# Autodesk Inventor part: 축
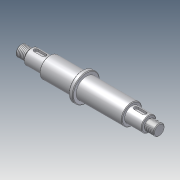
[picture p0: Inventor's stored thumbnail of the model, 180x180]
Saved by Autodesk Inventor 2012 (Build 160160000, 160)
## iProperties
Company: 한국ATC센터
Created: 2015-02
Part Number: 축
Document SubType Name: Modeling
Designer: KYOUNG IL JANG
Density: 1 g/cm^3
Material: 기본값
Author: KYOUNG IL JANG
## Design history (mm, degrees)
sketch "스케치1"
  geometry: L1 (0, 0)-(203, 0); L2 (203, 0)-(203, 8); L3 (203, 8)-(189.5, 8); L4 (189.5, 8)-(189.5, 7); L5 (189.5, 7)-(188, 7); L6 (188, 7)-(188, 11); L7 (188, 11)-(163, 11); L8 (163, 11)-(163, 15); L9 (163, 15)-(96, 15); L10 (96, 15)-(96, 20); L11 (96, 20)-(90, 20); L12 (90, 20)-(90, 15); L13 (90, 15)-(42, 15); L14 (42, 15)-(42, 11); L15 (42, 11)-(15, 11); L16 (15, 11)-(15, 7); L17 (15, 7)-(13.5, 7); L18 (0, 8)-(0, 0); L19 (0, 8)-(13.5, 8); L20 (13.5, 8)-(13.5, 7)
  constraints: 40 end point, 16 parallel, 3 perpendicular, 1 collinear, 1 horizontal
  dimensions: "d0" = 16 diameter of L3 L1; "d1" = 14 diameter of L5 L1; "d2" = 22 diameter of L7 L1; "d3" = 30 diameter of L9 L1; "d4" = 40 diameter of L11 L1; "d5" = 16 diameter of L19 L1; "d6" = 22 diameter of L15 L1; "d8" = 1.5 distance of L16.end L17.end; "d9" = 15 distance between parallel lines of L16 L18; "d10" = 27 distance between parallel lines of L14 L16; "d11" = 48 distance between parallel lines of L12 L14; "d15" = 203 distance of L1.start L1.end; "d16" = 1.5 distance of L4.end L5.end; "d17" = 14 diameter of L17 L1; "d36" = 15 distance between parallel lines of L6 L2; "d37" = 25 distance between parallel lines of L6 L8; "d38" = 6 distance between parallel lines of L10 L12
revolve "회전1" sketch "스케치1" stored, may be unused: angle "d18" = 90 deg
feature "스레드1" dims "d19" = 10, "d20" = 0
feature "스레드2" dims "d21" = 10, "d22" = 0
chamfer "모따기1" distance "d23" = 1; stored, may be unused: second distance "d24" = 2, angle "d25" = 45 deg
node "작업 평면1"
sketch "스케치2"
  geometry: L1 (-6.5, 3)-(5.5, 3); L2 (5.5, -3)-(-6.5, -3); L3 (-13.5, -10)-(-13.5, 10) reference; L4 (140.5, 3)-(152.5, 3); L5 (152.5, -3)-(140.5, -3); L6 (159.5, 10)-(159.5, -10) reference; A1 r 3 centre (5.5, 0) between (5.5, -3) and (5.5, 3); A2 r 3 centre (-6.5, 0) between (-6.5, 3) and (-6.5, -3); A3 r 3 centre (152.5, 0) between (152.5, -3) and (152.5, 3); A4 r 3 centre (140.5, 0) between (140.5, 3) and (140.5, -3); 1 further point
  constraints: 8 end point, 8 point on circle, 8 tangent, 4 centre point, 2 horizontal, 2 horizontal alignment, 2 parallel
  dimensions: "d26" = 6 distance between parallel lines of L2 L1; "d27" = 18 dimension on A1 A2; "d28" = 4 distance edge to line of A2 L3; "d29" = 6 distance between parallel lines of L5 L4; "d30" = 18 dimension on A3 A4; "d31" = 4 distance edge to line of A3 L6
extrude "돌출1" cut sketch "스케치2" distance "d32" = 3.5; taper "d33" = 0 deg
node "솔리드1"
